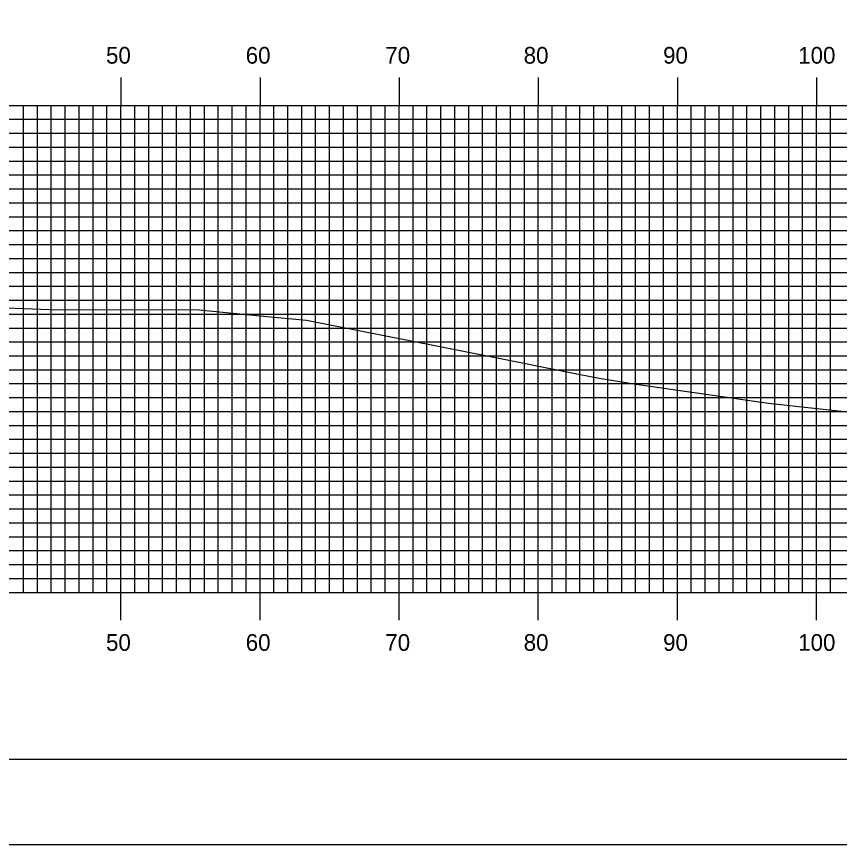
# Model space of a CAD drawing. Extents: x 852542 to 852886, y 364366 to 364586.
# Drawn here: x 852750.7 to 852809.8, y 364365.7 to 364425.2 of the extents above; entities that cross this region are included whole.
import ezdxf

# ---------------------------------------------------------------- set-up
doc = ezdxf.new("R2010")
doc.units = 0
for name, color, linetype in [('BORDER', 7, 'Continuous'), ('H_V ANNOTATION', 7, 'Continuous'), ('MAJOR', 7, 'Continuous'), ('MINOR', 7, 'Continuous'), ('PLOT BOUNDARY', 7, 'Continuous'), ('S_Roadway_Centerline', 7, 'Continuous')]:
    doc.layers.add(name, color=color, linetype=linetype)

msp = doc.modelspace()

# ---------------------------------------------------------------- linework, layer by layer
at = {"layer": 'BORDER'}
msp.add_lwpolyline([(852558.578, 364371.787), (852878.578, 364371.787), (852878.578, 364581.787), (852558.578, 364581.787)], close=True, dxfattribs=at)
at = {"layer": 'MAJOR'}
for p, q in [((852758.178, 364420.791), (852758.178, 364418.787)), ((852768.178, 364420.791), (852768.178, 364418.787)), ((852778.178, 364420.791), (852778.178, 364418.787)), ((852788.178, 364420.791), (852788.178, 364418.787)), ((852798.178, 364420.791), (852798.178, 364418.787)), ((852808.178, 364420.791), (852808.178, 364418.787)), ((852568.178, 364418.787), (852848.178, 364418.787)), ((852568.178, 364418.787), (852848.178, 364418.787)), ((852758.178, 364383.787), (852758.178, 364418.787)), ((852768.178, 364383.787), (852768.178, 364418.787)), ((852778.178, 364383.787), (852778.178, 364418.787)), ((852788.178, 364383.787), (852788.178, 364418.787)), ((852798.178, 364383.787), (852798.178, 364418.787)), ((852808.178, 364383.787), (852808.178, 364418.787)), ((852568.178, 364413.787), (852848.178, 364413.787)), ((852568.178, 364408.787), (852848.178, 364408.787)), ((852568.178, 364403.787), (852848.178, 364403.787)), ((852568.178, 364398.787), (852848.178, 364398.787)), ((852568.178, 364393.787), (852848.178, 364393.787)), ((852568.178, 364388.787), (852848.178, 364388.787)), ((852568.178, 364383.787), (852848.178, 364383.787)), ((852568.178, 364383.787), (852848.178, 364383.787)), ((852758.178, 364381.783), (852758.178, 364383.787)), ((852768.178, 364381.783), (852768.178, 364383.787)), ((852778.178, 364381.783), (852778.178, 364383.787)), ((852788.178, 364381.783), (852788.178, 364383.787)), ((852798.178, 364381.783), (852798.178, 364383.787)), ((852808.178, 364381.783), (852808.178, 364383.787))]:
    msp.add_line(p, q, dxfattribs=at)
at = {"layer": 'MINOR'}
for p, q in [((852751.178, 364383.787), (852751.178, 364418.787)), ((852752.178, 364383.787), (852752.178, 364418.787)), ((852753.178, 364383.787), (852753.178, 364418.787)), ((852754.178, 364383.787), (852754.178, 364418.787)), ((852755.178, 364383.787), (852755.178, 364418.787)), ((852756.178, 364383.787), (852756.178, 364418.787)), ((852757.178, 364383.787), (852757.178, 364418.787)), ((852759.178, 364383.787), (852759.178, 364418.787)), ((852760.178, 364383.787), (852760.178, 364418.787)), ((852761.178, 364383.787), (852761.178, 364418.787)), ((852762.178, 364383.787), (852762.178, 364418.787)), ((852763.178, 364383.787), (852763.178, 364418.787)), ((852764.178, 364383.787), (852764.178, 364418.787)), ((852765.178, 364383.787), (852765.178, 364418.787)), ((852766.178, 364383.787), (852766.178, 364418.787)), ((852767.178, 364383.787), (852767.178, 364418.787)), ((852769.178, 364383.787), (852769.178, 364418.787)), ((852770.178, 364383.787), (852770.178, 364418.787)), ((852771.178, 364383.787), (852771.178, 364418.787)), ((852772.178, 364383.787), (852772.178, 364418.787)), ((852773.178, 364383.787), (852773.178, 364418.787)), ((852774.178, 364383.787), (852774.178, 364418.787)), ((852775.178, 364383.787), (852775.178, 364418.787)), ((852776.178, 364383.787), (852776.178, 364418.787)), ((852777.178, 364383.787), (852777.178, 364418.787)), ((852779.178, 364383.787), (852779.178, 364418.787)), ((852780.178, 364383.787), (852780.178, 364418.787)), ((852781.178, 364383.787), (852781.178, 364418.787)), ((852782.178, 364383.787), (852782.178, 364418.787)), ((852783.178, 364383.787), (852783.178, 364418.787)), ((852784.178, 364383.787), (852784.178, 364418.787)), ((852785.178, 364383.787), (852785.178, 364418.787)), ((852786.178, 364383.787), (852786.178, 364418.787)), ((852787.178, 364383.787), (852787.178, 364418.787)), ((852789.178, 364383.787), (852789.178, 364418.787)), ((852790.178, 364383.787), (852790.178, 364418.787)), ((852791.178, 364383.787), (852791.178, 364418.787)), ((852792.178, 364383.787), (852792.178, 364418.787)), ((852793.178, 364383.787), (852793.178, 364418.787)), ((852794.178, 364383.787), (852794.178, 364418.787)), ((852795.178, 364383.787), (852795.178, 364418.787)), ((852796.178, 364383.787), (852796.178, 364418.787)), ((852797.178, 364383.787), (852797.178, 364418.787)), ((852799.178, 364383.787), (852799.178, 364418.787)), ((852800.178, 364383.787), (852800.178, 364418.787)), ((852801.178, 364383.787), (852801.178, 364418.787)), ((852802.178, 364383.787), (852802.178, 364418.787)), ((852803.178, 364383.787), (852803.178, 364418.787)), ((852804.178, 364383.787), (852804.178, 364418.787)), ((852805.178, 364383.787), (852805.178, 364418.787)), ((852806.178, 364383.787), (852806.178, 364418.787)), ((852807.178, 364383.787), (852807.178, 364418.787)), ((852809.178, 364383.787), (852809.178, 364418.787)), ((852568.178, 364417.787), (852848.178, 364417.787)), ((852568.178, 364416.787), (852848.178, 364416.787)), ((852568.178, 364415.787), (852848.178, 364415.787)), ((852568.178, 364414.787), (852848.178, 364414.787)), ((852568.178, 364412.787), (852848.178, 364412.787)), ((852568.178, 364411.787), (852848.178, 364411.787)), ((852568.178, 364410.787), (852848.178, 364410.787)), ((852568.178, 364409.787), (852848.178, 364409.787)), ((852568.178, 364407.787), (852848.178, 364407.787)), ((852568.178, 364406.787), (852848.178, 364406.787)), ((852568.178, 364405.787), (852848.178, 364405.787)), ((852568.178, 364404.787), (852848.178, 364404.787)), ((852568.178, 364402.787), (852848.178, 364402.787)), ((852568.178, 364401.787), (852848.178, 364401.787)), ((852568.178, 364400.787), (852848.178, 364400.787)), ((852568.178, 364399.787), (852848.178, 364399.787)), ((852568.178, 364397.787), (852848.178, 364397.787)), ((852568.178, 364396.787), (852848.178, 364396.787)), ((852568.178, 364395.787), (852848.178, 364395.787)), ((852568.178, 364394.787), (852848.178, 364394.787)), ((852568.178, 364392.787), (852848.178, 364392.787)), ((852568.178, 364391.787), (852848.178, 364391.787)), ((852568.178, 364390.787), (852848.178, 364390.787)), ((852568.178, 364389.787), (852848.178, 364389.787)), ((852568.178, 364387.787), (852848.178, 364387.787)), ((852568.178, 364386.787), (852848.178, 364386.787)), ((852568.178, 364385.787), (852848.178, 364385.787)), ((852568.178, 364384.787), (852848.178, 364384.787))]:
    msp.add_line(p, q, dxfattribs=at)
at = {"layer": 'PLOT BOUNDARY'}
msp.add_lwpolyline([(852542.392, 364365.669), (852882.392, 364365.669), (852882.392, 364585.669), (852542.392, 364585.669)], close=True, dxfattribs=at)
at = {"layer": 'S_Roadway_Centerline'}
msp.add_lwpolyline([(852688.559, 364399.681), (852700.745, 364402.23), (852709.021, 364403.295), (852713.555, 364404.197), (852730.362, 364404.925), (852731.345, 364404.917), (852732.055, 364404.933), (852753.053, 364404.106), (852763.798, 364404.097), (852768.436, 364403.632), (852771.519, 364403.34), (852784.623, 364400.763), (852790.954, 364399.495), (852792.561, 364399.185), (852795.206, 364398.758), (852804.722, 364397.391), (852810.397, 364396.754), (852825.7, 364395.636), (852828.854, 364395.467), (852839.509, 364395.389), (852847.407, 364395.342), (852848.178, 364395.458)], dxfattribs=at)

# ---------------------------------------------------------------- texts
at = {"layer": 'H_V ANNOTATION'}
for s, p in [('50', (852757.108, 364421.787)), ('60', (852767.151, 364421.787)), ('70', (852777.182, 364421.787)), ('80', (852787.129, 364421.787)), ('90', (852797.151, 364421.787)), ('100', (852806.862, 364421.787)), ('50', (852757.108, 364379.587)), ('60', (852767.151, 364379.587)), ('70', (852777.182, 364379.587)), ('80', (852787.129, 364379.587)), ('90', (852797.151, 364379.587)), ('100', (852806.862, 364379.587))]:
    msp.add_text(s, height=1.2, dxfattribs=at).set_placement(p)

doc.saveas('drawing.dxf')
